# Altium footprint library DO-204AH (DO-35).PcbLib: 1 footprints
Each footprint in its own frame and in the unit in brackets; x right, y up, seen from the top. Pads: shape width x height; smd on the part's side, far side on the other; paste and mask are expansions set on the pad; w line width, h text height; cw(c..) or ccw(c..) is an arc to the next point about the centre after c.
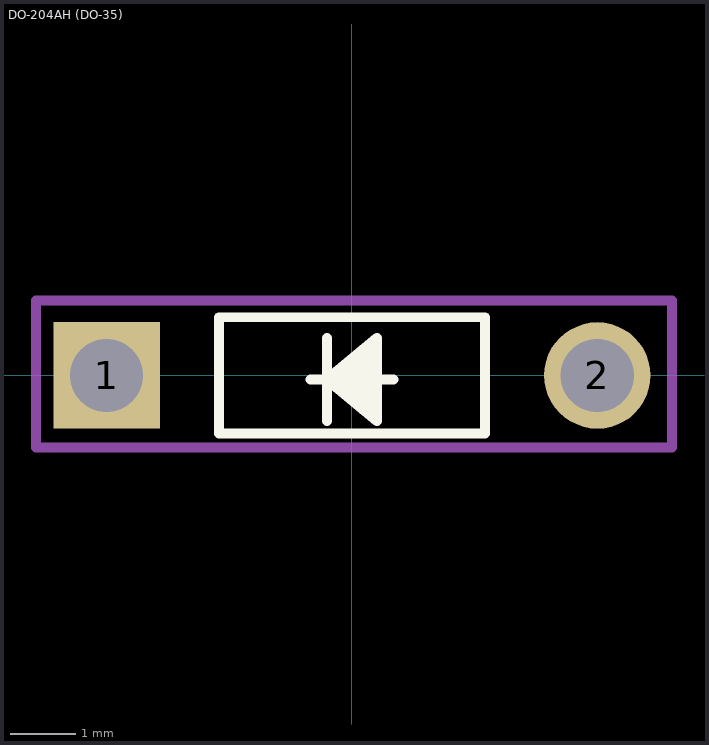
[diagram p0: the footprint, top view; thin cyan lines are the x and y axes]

## DO-204AH (DO-35) [mil]
pads (2):
  rect 64x64 hole 44: 1(-147.5,0)
  round 64 hole 44: 2(147.5,0)
Top Overlay:
  lines w6: -25,-2.5 25,-2.5 ; -15,-27.5 -15,22.5 ; 15,-22.5 -15,-2.5 ; 15,-17.5 -15,-2.5 ; 15,-12.5 -15,-2.5 ; 15,-7.5 -15,-2.5 ; 15,2.5 -15,-2.5 ; 15,7.5 -15,-2.5 ; 15,12.5 -15,-2.5 ; 15,17.5 -15,-2.5 ; -15,-2.5 15,-27.5 15,22.5 -15,-2.5 ; -80,-35 -80,35 80,35 80,-35 -80,-35
Mechanical 15:
  lines w6: -190,-43.22 121.28,-43.22 192.5,-43.22 192.5,45 104.5,45 -190,45 -190,-43.22
3D body "User Library-DO-35G-30.step": height 111.06, standoff -39.37, extent -165.83,-35.21 155.83,35.21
